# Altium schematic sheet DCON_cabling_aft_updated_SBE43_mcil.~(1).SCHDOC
size B
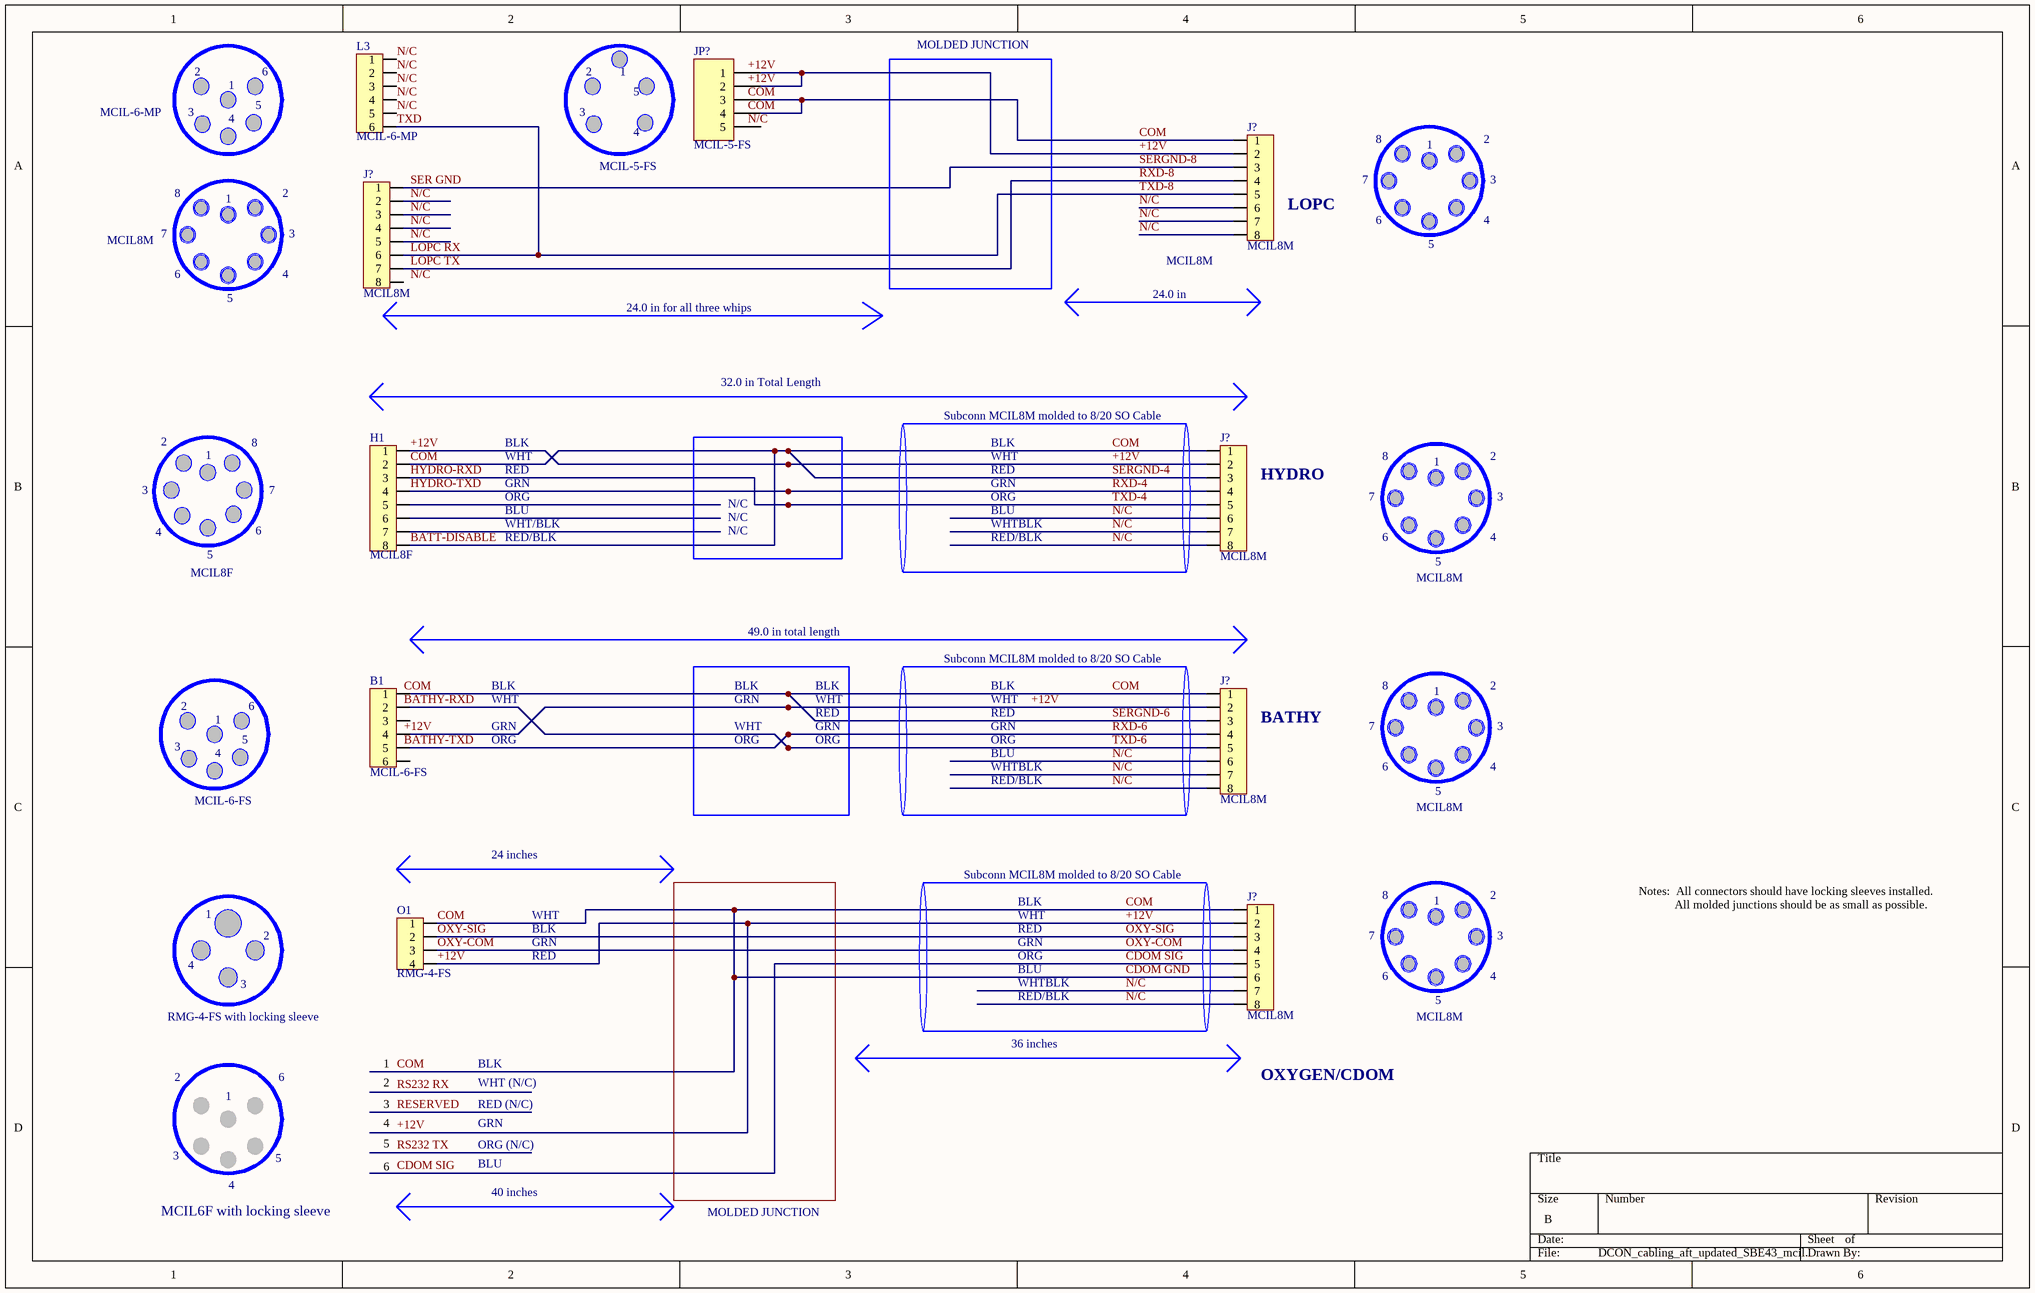
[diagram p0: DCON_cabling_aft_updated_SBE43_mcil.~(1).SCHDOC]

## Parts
(Parts that share a designator on the sheet are numbered #1, #2 ... from top to bottom, then left to right.)
*  (no value)  [None Available]
B1  MCIL-6-FS  [SIP6]
H1  MCIL8F  [SIP6]
J?#1  MCIL8M  [SIP8]
J?#2  MCIL8M  [SIP8]
J?#3  MCIL8M  [SIP8]
J?#4  MCIL8M  [SIP8]
J?#5  MCIL8M  [SIP8]
JP?  MCIL-5-FS  [HDR1X5]
L3  MCIL-6-MP  [SIP6]
O1  RMG-4-FS  [SIP6]

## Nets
+12V: B1.4 H1.1 J?#1.2 J?#3.2 J?#4.2 J?#5.2 JP?.1 JP?.2 O1.4
BATT-DISABLE: B1.1 H1.2 H1.8 J?#1.1 J?#3.1 J?#3.3 J?#4.1 J?#4.3 J?#5.1 J?#5.6 JP?.3 JP?.4 O1.1  [also labelled CDOM GND, COM, SERGND-4, SERGND-6]
CDOM SIG: J?#5.5
HYDRO-RXD: H1.3 J?#3.5  [also labelled TXD-4]
HYDRO-TXD: H1.4 J?#3.4  [also labelled RXD-4]
N/C: J?#1.6 J?#1.7 J?#1.8 J?#2.2 J?#2.3 J?#2.4 J?#2.5 J?#3.6 J?#3.7 J?#3.8 J?#4.6 J?#4.7 J?#4.8 J?#5.7 J?#5.8 L3.1 L3.2 L3.3 L3.4 L3.5
OXY-COM: J?#5.4 O1.3
OXY-SIG: J?#5.3 O1.2
RXD-6: B1.5 J?#4.4
RXD-8: J?#1.4 J?#2.7
SERGND-8: J?#1.3 J?#2.1
TXD: J?#1.5 J?#2.6 L3.6  [also labelled TXD-8]
TXD-6: B1.2 J?#4.5

Not connected (* = marked no-connect by the designer): B1 3 6; H1 5 6 7; J?#2 8; JP? 5

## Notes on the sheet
- 2
- 1
- 6
- 5
- MOLDED JUNCTION
- MCIL-6-MP
- 3
- 4
- 8
- 7
- (near J?#2) SER GND
- MCIL-5-FS
- (near J?#1) LOPC
- MCIL8M
- (near J?#2) LOPC RX
- (near J?#2) LOPC TX
- (near J?#2) N/C
- 24.0 in
- (near J?#1) MCIL8M
- 24.0 in for all three whips
- 32.0 in Total Length
- (near J?#3) Subconn MCIL8M molded to 8/20 SO Cable
- BLK
- WHT
- RED
- GRN
- ORG
- N/C
- (near J?#3) HYDRO
- BLU
- WHT/BLK
- RED/BLK
- WHTBLK
- MCIL8F
- 49.0 in total length
- (near J?#4) Subconn MCIL8M molded to 8/20 SO Cable
- (near J?#4) BATHY
- MCIL-6-FS
- 24 inches
- Subconn MCIL8M molded to 8/20 SO Cable
- RMG-4-FS with locking sleeve
- 36 inches
- WHT (N/C)
- RED (N/C)
- OXYGEN/CDOM
- Notes:  All connectors should have locking sleeves installed.
  All molded junctions should be as small as possible.
- ORG (N/C)
- MCIL6F with locking sleeve
- 40 inches
- Labels drawn without touching a wire or pin: +12V, BATHY-RXD, BATHY-TXD, COM, N/C

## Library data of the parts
* = MCIL6F
B1 L3 = CON6: Connector
H1 = CON8: Connector
J?#1-J?#5 = CON8: Connector; ManufPartNo: MCIL8M molded to 24"  8/20 SO Cable; Manufacturer: Subconn
JP? = Header 5: Header, 5-Pin; Manufacturer: Generic Components; Class I: Connector
O1 = CON4: Connector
